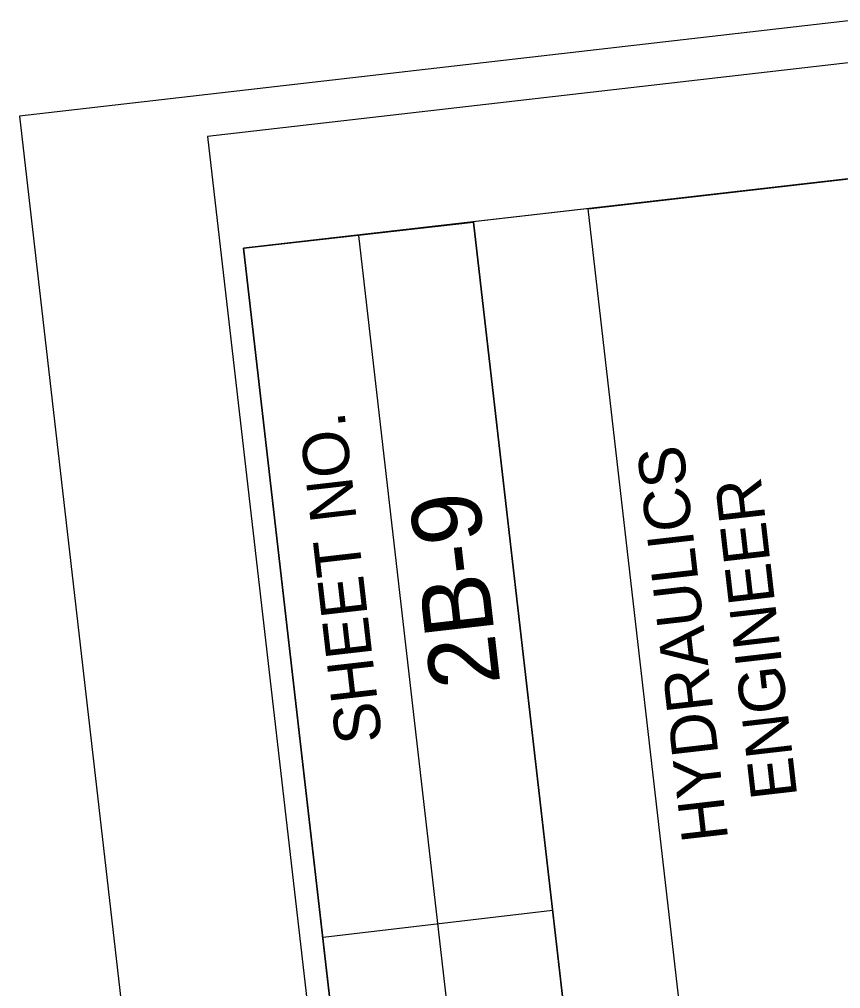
# Model space of a CAD drawing. Extents: x 474105 to 475385, y 502977 to 504774.
# Drawn here: x 474105.4 to 474194.3, y 504554.8 to 504659.7 of the extents above; entities that cross this region are included whole.
import ezdxf

# ---------------------------------------------------------------- set-up
doc = ezdxf.new("R2010")
doc.units = 0
for name, color, linetype in [('Sheet Cutting Line CELL', 7, 'Continuous'), ('Sheet Data Field CELL', 7, 'Continuous'), ('Sheet Plan CELL', 7, 'Continuous'), ('Sheet Plan Layout CELL', 7, 'Continuous'), ('Sheet Plot Border Inside CELL', 7, 'Continuous'), ('Sheet Plot Border Outside CELL', 7, 'Continuous')]:
    doc.layers.add(name, color=color, linetype=linetype)

msp = doc.modelspace()

# ---------------------------------------------------------------- linework, layer by layer
at = {"layer": 'Sheet Cutting Line CELL'}
msp.add_line((474105.4, 504649.22), (474297.55, 502976.72), dxfattribs=at)
at = {"layer": 'Sheet Plan CELL'}
for p, q in [((474177.42, 504439.01), (474154.57, 504637.74)), ((474177.42, 504439.01), (474154.57, 504637.74)), ((474164.97, 504437.57), (474142.15, 504636.31)), ((474138.3, 504560.35), (474163.14, 504563.26))]:
    msp.add_line(p, q, dxfattribs=at)
for points in [[(474129.67, 504634.92), (474300.88, 503144.68), (475344.02, 503264.53), (475172.82, 504754.74)], [(474178.41, 504539.84), (474166.98, 504639.17), (474278.76, 504652.02), (474290.19, 504552.68)], [(474152.5, 504436.15), (474129.67, 504634.92), (474154.57, 504637.74), (474177.42, 504439.01)]]:
    msp.add_lwpolyline(points, close=True, dxfattribs=at)
at = {"layer": 'Sheet Plan Layout CELL'}
msp.add_lwpolyline([(474367.09, 504421.33), (474339.78, 504659.05), (474129.67, 504634.93), (474156.99, 504397.2)], close=True, dxfattribs=at)
at = {"layer": 'Sheet Plot Border Inside CELL'}
msp.add_lwpolyline([(475364.04, 503112.33), (475173.87, 504767.43), (474125.78, 504647.03), (474315.93, 502991.92)], close=True, dxfattribs=at)
at = {"layer": 'Sheet Plot Border Outside CELL'}
msp.add_lwpolyline([(475385.39, 503101.7), (475193.24, 504774.2), (474105.4, 504649.22), (474297.55, 502976.72)], close=True, dxfattribs=at)

# ---------------------------------------------------------------- texts
at = {"layer": 'Sheet Data Field CELL'}
msp.add_text('2B-9', height=7.5, rotation=96.5538, dxfattribs=at).set_placement((474157.48, 504587.8))
at = {"layer": 'Sheet Plan CELL'}
for s, p in [('SHEET NO.', (474144.69, 504581.57)), ('HYDRAULICS', (474182.16, 504570.93)), ('ENGINEER', (474189.64, 504575.58))]:
    msp.add_text(s, height=5, rotation=96.5538, dxfattribs=at).set_placement(p)

doc.saveas('drawing.dxf')
